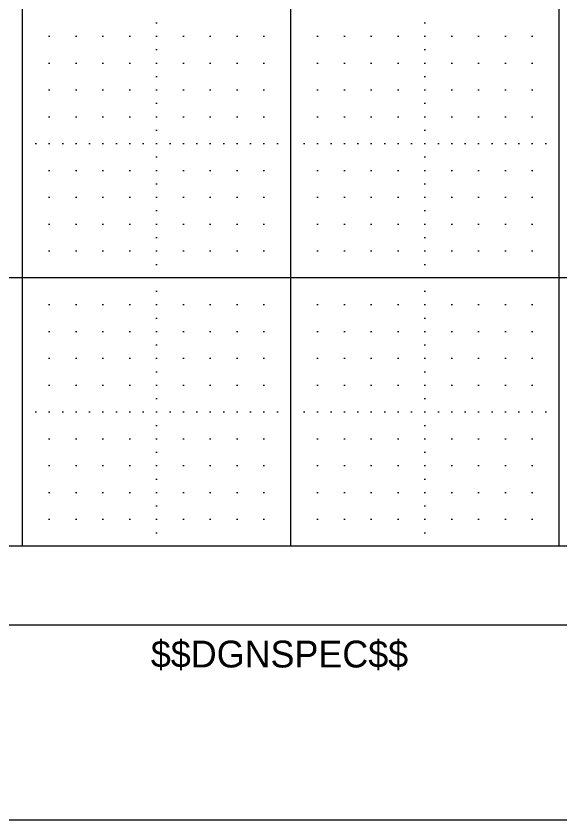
# Model space of a CAD drawing. Extents: x -1.6 to 32.7, y -1.7 to 21.9.
# Drawn here: x 21.721 to 23.748, y -0.727 to 2.268 of the extents above; entities that cross this region are included whole.
import ezdxf

# ---------------------------------------------------------------- set-up
doc = ezdxf.new("R2010")
doc.units = 0
for name, color, linetype in [('Level 1', 7, 'Continuous'), ('Level 4', 7, 'Continuous'), ('Level 48', 7, 'Continuous'), ('Level 5', 7, 'Continuous'), ('Level 63', 7, 'Continuous'), ('R_Border_Dark', 7, 'Continuous')]:
    doc.layers.add(name, color=color, linetype=linetype)

msp = doc.modelspace()

# ---------------------------------------------------------------- linework, layer by layer
at = {"layer": 'Level 1'}
msp.add_line((31.617, -0.001), (-0.001, -0.001), dxfattribs=at)
msp.add_lwpolyline([(0.745, 11.3072), (30.745, 11.3072), (30.745, 0.293), (0.745, 0.293)], close=True, dxfattribs=at)
at = {"layer": 'Level 4'}
msp.add_line((31.617, 0.293), (-0.001, 0.293), dxfattribs=at)
at = {"layer": 'Level 5'}
for p, q in [((22.2425, 2.243), (22.2475, 2.243)), ((23.2425, 2.243), (23.2475, 2.243)), ((21.8425, 2.193), (21.8475, 2.193)), ((21.9425, 2.193), (21.9475, 2.193)), ((22.0425, 2.193), (22.0475, 2.193)), ((22.1425, 2.193), (22.1475, 2.193)), ((22.2425, 2.193), (22.2475, 2.193)), ((22.3425, 2.193), (22.3475, 2.193)), ((22.4425, 2.193), (22.4475, 2.193)), ((22.5425, 2.193), (22.5475, 2.193)), ((22.6425, 2.193), (22.6475, 2.193)), ((22.8425, 2.193), (22.8475, 2.193)), ((22.9425, 2.193), (22.9475, 2.193)), ((23.0425, 2.193), (23.0475, 2.193)), ((23.1425, 2.193), (23.1475, 2.193)), ((23.2425, 2.193), (23.2475, 2.193)), ((23.3425, 2.193), (23.3475, 2.193)), ((23.4425, 2.193), (23.4475, 2.193)), ((23.5425, 2.193), (23.5475, 2.193)), ((23.6425, 2.193), (23.6475, 2.193)), ((22.2425, 2.143), (22.2475, 2.143)), ((23.2425, 2.143), (23.2475, 2.143)), ((21.8425, 2.093), (21.8475, 2.093)), ((21.9425, 2.093), (21.9475, 2.093)), ((22.0425, 2.093), (22.0475, 2.093)), ((22.1425, 2.093), (22.1475, 2.093)), ((22.2425, 2.093), (22.2475, 2.093)), ((22.3425, 2.093), (22.3475, 2.093)), ((22.4425, 2.093), (22.4475, 2.093)), ((22.5425, 2.093), (22.5475, 2.093)), ((22.6425, 2.093), (22.6475, 2.093)), ((22.8425, 2.093), (22.8475, 2.093)), ((22.9425, 2.093), (22.9475, 2.093)), ((23.0425, 2.093), (23.0475, 2.093)), ((23.1425, 2.093), (23.1475, 2.093)), ((23.2425, 2.093), (23.2475, 2.093)), ((23.3425, 2.093), (23.3475, 2.093)), ((23.4425, 2.093), (23.4475, 2.093)), ((23.5425, 2.093), (23.5475, 2.093)), ((23.6425, 2.093), (23.6475, 2.093)), ((22.2425, 2.043), (22.2475, 2.043)), ((23.2425, 2.043), (23.2475, 2.043)), ((21.8425, 1.993), (21.8475, 1.993)), ((21.9425, 1.993), (21.9475, 1.993)), ((22.0425, 1.993), (22.0475, 1.993)), ((22.1425, 1.993), (22.1475, 1.993)), ((22.2425, 1.993), (22.2475, 1.993)), ((22.3425, 1.993), (22.3475, 1.993)), ((22.4425, 1.993), (22.4475, 1.993)), ((22.5425, 1.993), (22.5475, 1.993)), ((22.6425, 1.993), (22.6475, 1.993)), ((22.8425, 1.993), (22.8475, 1.993)), ((22.9425, 1.993), (22.9475, 1.993)), ((23.0425, 1.993), (23.0475, 1.993)), ((23.1425, 1.993), (23.1475, 1.993)), ((23.2425, 1.993), (23.2475, 1.993)), ((23.3425, 1.993), (23.3475, 1.993)), ((23.4425, 1.993), (23.4475, 1.993)), ((23.5425, 1.993), (23.5475, 1.993)), ((23.6425, 1.993), (23.6475, 1.993)), ((22.2425, 1.943), (22.2475, 1.943)), ((23.2425, 1.943), (23.2475, 1.943)), ((21.8425, 1.893), (21.8475, 1.893)), ((21.9425, 1.893), (21.9475, 1.893)), ((22.0425, 1.893), (22.0475, 1.893)), ((22.1425, 1.893), (22.1475, 1.893)), ((22.2425, 1.893), (22.2475, 1.893)), ((22.3425, 1.893), (22.3475, 1.893)), ((22.4425, 1.893), (22.4475, 1.893)), ((22.5425, 1.893), (22.5475, 1.893)), ((22.6425, 1.893), (22.6475, 1.893)), ((22.8425, 1.893), (22.8475, 1.893)), ((22.9425, 1.893), (22.9475, 1.893)), ((23.0425, 1.893), (23.0475, 1.893)), ((23.1425, 1.893), (23.1475, 1.893)), ((23.2425, 1.893), (23.2475, 1.893)), ((23.3425, 1.893), (23.3475, 1.893)), ((23.4425, 1.893), (23.4475, 1.893)), ((23.5425, 1.893), (23.5475, 1.893)), ((23.6425, 1.893), (23.6475, 1.893)), ((22.2425, 1.843), (22.2475, 1.843)), ((23.2425, 1.843), (23.2475, 1.843)), ((21.7925, 1.793), (21.7975, 1.793)), ((21.8425, 1.793), (21.8475, 1.793)), ((21.8925, 1.793), (21.8975, 1.793)), ((21.9425, 1.793), (21.9475, 1.793)), ((21.9925, 1.793), (21.9975, 1.793)), ((22.0425, 1.793), (22.0475, 1.793)), ((22.0925, 1.793), (22.0975, 1.793)), ((22.1425, 1.793), (22.1475, 1.793)), ((22.1925, 1.793), (22.1975, 1.793)), ((22.2425, 1.793), (22.2475, 1.793)), ((22.2925, 1.793), (22.2975, 1.793)), ((22.3425, 1.793), (22.3475, 1.793)), ((22.3925, 1.793), (22.3975, 1.793)), ((22.4425, 1.793), (22.4475, 1.793)), ((22.4925, 1.793), (22.4975, 1.793)), ((22.5425, 1.793), (22.5475, 1.793)), ((22.5925, 1.793), (22.5975, 1.793)), ((22.6425, 1.793), (22.6475, 1.793)), ((22.6925, 1.793), (22.6975, 1.793)), ((22.7925, 1.793), (22.7975, 1.793)), ((22.8425, 1.793), (22.8475, 1.793)), ((22.8925, 1.793), (22.8975, 1.793)), ((22.9425, 1.793), (22.9475, 1.793)), ((22.9925, 1.793), (22.9975, 1.793)), ((23.0425, 1.793), (23.0475, 1.793)), ((23.0925, 1.793), (23.0975, 1.793)), ((23.1425, 1.793), (23.1475, 1.793)), ((23.1925, 1.793), (23.1975, 1.793)), ((23.2425, 1.793), (23.2475, 1.793)), ((23.2925, 1.793), (23.2975, 1.793)), ((23.3425, 1.793), (23.3475, 1.793)), ((23.3925, 1.793), (23.3975, 1.793)), ((23.4425, 1.793), (23.4475, 1.793)), ((23.4925, 1.793), (23.4975, 1.793)), ((23.5425, 1.793), (23.5475, 1.793)), ((23.5925, 1.793), (23.5975, 1.793)), ((23.6425, 1.793), (23.6475, 1.793)), ((23.6925, 1.793), (23.6975, 1.793)), ((22.2425, 1.743), (22.2475, 1.743)), ((23.2425, 1.743), (23.2475, 1.743)), ((21.8425, 1.693), (21.8475, 1.693)), ((21.9425, 1.693), (21.9475, 1.693)), ((22.0425, 1.693), (22.0475, 1.693)), ((22.1425, 1.693), (22.1475, 1.693)), ((22.2425, 1.693), (22.2475, 1.693)), ((22.3425, 1.693), (22.3475, 1.693)), ((22.4425, 1.693), (22.4475, 1.693)), ((22.5425, 1.693), (22.5475, 1.693)), ((22.6425, 1.693), (22.6475, 1.693)), ((22.8425, 1.693), (22.8475, 1.693)), ((22.9425, 1.693), (22.9475, 1.693)), ((23.0425, 1.693), (23.0475, 1.693)), ((23.1425, 1.693), (23.1475, 1.693)), ((23.2425, 1.693), (23.2475, 1.693)), ((23.3425, 1.693), (23.3475, 1.693)), ((23.4425, 1.693), (23.4475, 1.693)), ((23.5425, 1.693), (23.5475, 1.693)), ((23.6425, 1.693), (23.6475, 1.693)), ((22.2425, 1.643), (22.2475, 1.643)), ((23.2425, 1.643), (23.2475, 1.643)), ((21.8425, 1.593), (21.8475, 1.593)), ((21.9425, 1.593), (21.9475, 1.593)), ((22.0425, 1.593), (22.0475, 1.593)), ((22.1425, 1.593), (22.1475, 1.593)), ((22.2425, 1.593), (22.2475, 1.593)), ((22.3425, 1.593), (22.3475, 1.593)), ((22.4425, 1.593), (22.4475, 1.593)), ((22.5425, 1.593), (22.5475, 1.593)), ((22.6425, 1.593), (22.6475, 1.593)), ((22.8425, 1.593), (22.8475, 1.593)), ((22.9425, 1.593), (22.9475, 1.593)), ((23.0425, 1.593), (23.0475, 1.593)), ((23.1425, 1.593), (23.1475, 1.593)), ((23.2425, 1.593), (23.2475, 1.593)), ((23.3425, 1.593), (23.3475, 1.593)), ((23.4425, 1.593), (23.4475, 1.593)), ((23.5425, 1.593), (23.5475, 1.593)), ((23.6425, 1.593), (23.6475, 1.593)), ((22.2425, 1.543), (22.2475, 1.543)), ((23.2425, 1.543), (23.2475, 1.543)), ((21.8425, 1.493), (21.8475, 1.493)), ((21.9425, 1.493), (21.9475, 1.493)), ((22.0425, 1.493), (22.0475, 1.493)), ((22.1425, 1.493), (22.1475, 1.493)), ((22.2425, 1.493), (22.2475, 1.493)), ((22.3425, 1.493), (22.3475, 1.493)), ((22.4425, 1.493), (22.4475, 1.493)), ((22.5425, 1.493), (22.5475, 1.493)), ((22.6425, 1.493), (22.6475, 1.493)), ((22.8425, 1.493), (22.8475, 1.493)), ((22.9425, 1.493), (22.9475, 1.493)), ((23.0425, 1.493), (23.0475, 1.493)), ((23.1425, 1.493), (23.1475, 1.493)), ((23.2425, 1.493), (23.2475, 1.493)), ((23.3425, 1.493), (23.3475, 1.493)), ((23.4425, 1.493), (23.4475, 1.493)), ((23.5425, 1.493), (23.5475, 1.493)), ((23.6425, 1.493), (23.6475, 1.493)), ((22.2425, 1.443), (22.2475, 1.443)), ((23.2425, 1.443), (23.2475, 1.443)), ((21.8425, 1.393), (21.8475, 1.393)), ((21.9425, 1.393), (21.9475, 1.393)), ((22.0425, 1.393), (22.0475, 1.393)), ((22.1425, 1.393), (22.1475, 1.393)), ((22.2425, 1.393), (22.2475, 1.393)), ((22.3425, 1.393), (22.3475, 1.393)), ((22.4425, 1.393), (22.4475, 1.393)), ((22.5425, 1.393), (22.5475, 1.393)), ((22.6425, 1.393), (22.6475, 1.393)), ((22.8425, 1.393), (22.8475, 1.393)), ((22.9425, 1.393), (22.9475, 1.393)), ((23.0425, 1.393), (23.0475, 1.393)), ((23.1425, 1.393), (23.1475, 1.393)), ((23.2425, 1.393), (23.2475, 1.393)), ((23.3425, 1.393), (23.3475, 1.393)), ((23.4425, 1.393), (23.4475, 1.393)), ((23.5425, 1.393), (23.5475, 1.393)), ((23.6425, 1.393), (23.6475, 1.393)), ((22.2425, 1.343), (22.2475, 1.343)), ((23.2425, 1.343), (23.2475, 1.343)), ((22.2425, 1.243), (22.2475, 1.243)), ((23.2425, 1.243), (23.2475, 1.243)), ((21.8425, 1.193), (21.8475, 1.193)), ((21.9425, 1.193), (21.9475, 1.193)), ((22.0425, 1.193), (22.0475, 1.193)), ((22.1425, 1.193), (22.1475, 1.193)), ((22.2425, 1.193), (22.2475, 1.193)), ((22.3425, 1.193), (22.3475, 1.193)), ((22.4425, 1.193), (22.4475, 1.193)), ((22.5425, 1.193), (22.5475, 1.193)), ((22.6425, 1.193), (22.6475, 1.193)), ((22.8425, 1.193), (22.8475, 1.193)), ((22.9425, 1.193), (22.9475, 1.193)), ((23.0425, 1.193), (23.0475, 1.193)), ((23.1425, 1.193), (23.1475, 1.193)), ((23.2425, 1.193), (23.2475, 1.193)), ((23.3425, 1.193), (23.3475, 1.193)), ((23.4425, 1.193), (23.4475, 1.193)), ((23.5425, 1.193), (23.5475, 1.193)), ((23.6425, 1.193), (23.6475, 1.193)), ((22.2425, 1.143), (22.2475, 1.143)), ((23.2425, 1.143), (23.2475, 1.143)), ((21.8425, 1.093), (21.8475, 1.093)), ((21.9425, 1.093), (21.9475, 1.093)), ((22.0425, 1.093), (22.0475, 1.093)), ((22.1425, 1.093), (22.1475, 1.093)), ((22.2425, 1.093), (22.2475, 1.093)), ((22.3425, 1.093), (22.3475, 1.093)), ((22.4425, 1.093), (22.4475, 1.093)), ((22.5425, 1.093), (22.5475, 1.093)), ((22.6425, 1.093), (22.6475, 1.093)), ((22.8425, 1.093), (22.8475, 1.093)), ((22.9425, 1.093), (22.9475, 1.093)), ((23.0425, 1.093), (23.0475, 1.093)), ((23.1425, 1.093), (23.1475, 1.093)), ((23.2425, 1.093), (23.2475, 1.093)), ((23.3425, 1.093), (23.3475, 1.093)), ((23.4425, 1.093), (23.4475, 1.093)), ((23.5425, 1.093), (23.5475, 1.093)), ((23.6425, 1.093), (23.6475, 1.093)), ((22.2425, 1.043), (22.2475, 1.043)), ((23.2425, 1.043), (23.2475, 1.043)), ((21.8425, 0.993), (21.8475, 0.993)), ((21.9425, 0.993), (21.9475, 0.993)), ((22.0425, 0.993), (22.0475, 0.993)), ((22.1425, 0.993), (22.1475, 0.993)), ((22.2425, 0.993), (22.2475, 0.993)), ((22.3425, 0.993), (22.3475, 0.993)), ((22.4425, 0.993), (22.4475, 0.993)), ((22.5425, 0.993), (22.5475, 0.993)), ((22.6425, 0.993), (22.6475, 0.993)), ((22.8425, 0.993), (22.8475, 0.993)), ((22.9425, 0.993), (22.9475, 0.993)), ((23.0425, 0.993), (23.0475, 0.993)), ((23.1425, 0.993), (23.1475, 0.993)), ((23.2425, 0.993), (23.2475, 0.993)), ((23.3425, 0.993), (23.3475, 0.993)), ((23.4425, 0.993), (23.4475, 0.993)), ((23.5425, 0.993), (23.5475, 0.993)), ((23.6425, 0.993), (23.6475, 0.993)), ((22.2425, 0.943), (22.2475, 0.943)), ((23.2425, 0.943), (23.2475, 0.943)), ((21.8425, 0.893), (21.8475, 0.893)), ((21.9425, 0.893), (21.9475, 0.893)), ((22.0425, 0.893), (22.0475, 0.893)), ((22.1425, 0.893), (22.1475, 0.893)), ((22.2425, 0.893), (22.2475, 0.893)), ((22.3425, 0.893), (22.3475, 0.893)), ((22.4425, 0.893), (22.4475, 0.893)), ((22.5425, 0.893), (22.5475, 0.893)), ((22.6425, 0.893), (22.6475, 0.893)), ((22.8425, 0.893), (22.8475, 0.893)), ((22.9425, 0.893), (22.9475, 0.893)), ((23.0425, 0.893), (23.0475, 0.893)), ((23.1425, 0.893), (23.1475, 0.893)), ((23.2425, 0.893), (23.2475, 0.893)), ((23.3425, 0.893), (23.3475, 0.893)), ((23.4425, 0.893), (23.4475, 0.893)), ((23.5425, 0.893), (23.5475, 0.893)), ((23.6425, 0.893), (23.6475, 0.893)), ((22.2425, 0.843), (22.2475, 0.843)), ((23.2425, 0.843), (23.2475, 0.843)), ((21.7925, 0.793), (21.7975, 0.793)), ((21.8425, 0.793), (21.8475, 0.793)), ((21.8925, 0.793), (21.8975, 0.793)), ((21.9425, 0.793), (21.9475, 0.793)), ((21.9925, 0.793), (21.9975, 0.793)), ((22.0425, 0.793), (22.0475, 0.793)), ((22.0925, 0.793), (22.0975, 0.793)), ((22.1425, 0.793), (22.1475, 0.793)), ((22.1925, 0.793), (22.1975, 0.793)), ((22.2425, 0.793), (22.2475, 0.793)), ((22.2925, 0.793), (22.2975, 0.793)), ((22.3425, 0.793), (22.3475, 0.793)), ((22.3925, 0.793), (22.3975, 0.793)), ((22.4425, 0.793), (22.4475, 0.793)), ((22.4925, 0.793), (22.4975, 0.793)), ((22.5425, 0.793), (22.5475, 0.793)), ((22.5925, 0.793), (22.5975, 0.793)), ((22.6425, 0.793), (22.6475, 0.793)), ((22.6925, 0.793), (22.6975, 0.793)), ((22.7925, 0.793), (22.7975, 0.793)), ((22.8425, 0.793), (22.8475, 0.793)), ((22.8925, 0.793), (22.8975, 0.793)), ((22.9425, 0.793), (22.9475, 0.793)), ((22.9925, 0.793), (22.9975, 0.793)), ((23.0425, 0.793), (23.0475, 0.793)), ((23.0925, 0.793), (23.0975, 0.793)), ((23.1425, 0.793), (23.1475, 0.793)), ((23.1925, 0.793), (23.1975, 0.793)), ((23.2425, 0.793), (23.2475, 0.793)), ((23.2925, 0.793), (23.2975, 0.793)), ((23.3425, 0.793), (23.3475, 0.793)), ((23.3925, 0.793), (23.3975, 0.793)), ((23.4425, 0.793), (23.4475, 0.793)), ((23.4925, 0.793), (23.4975, 0.793)), ((23.5425, 0.793), (23.5475, 0.793)), ((23.5925, 0.793), (23.5975, 0.793)), ((23.6425, 0.793), (23.6475, 0.793)), ((23.6925, 0.793), (23.6975, 0.793)), ((22.2425, 0.743), (22.2475, 0.743)), ((23.2425, 0.743), (23.2475, 0.743)), ((21.8425, 0.693), (21.8475, 0.693)), ((21.9425, 0.693), (21.9475, 0.693)), ((22.0425, 0.693), (22.0475, 0.693)), ((22.1425, 0.693), (22.1475, 0.693)), ((22.2425, 0.693), (22.2475, 0.693)), ((22.3425, 0.693), (22.3475, 0.693)), ((22.4425, 0.693), (22.4475, 0.693)), ((22.5425, 0.693), (22.5475, 0.693)), ((22.6425, 0.693), (22.6475, 0.693)), ((22.8425, 0.693), (22.8475, 0.693)), ((22.9425, 0.693), (22.9475, 0.693)), ((23.0425, 0.693), (23.0475, 0.693)), ((23.1425, 0.693), (23.1475, 0.693)), ((23.2425, 0.693), (23.2475, 0.693)), ((23.3425, 0.693), (23.3475, 0.693)), ((23.4425, 0.693), (23.4475, 0.693)), ((23.5425, 0.693), (23.5475, 0.693)), ((23.6425, 0.693), (23.6475, 0.693)), ((22.2425, 0.643), (22.2475, 0.643)), ((23.2425, 0.643), (23.2475, 0.643)), ((21.8425, 0.593), (21.8475, 0.593)), ((21.9425, 0.593), (21.9475, 0.593)), ((22.0425, 0.593), (22.0475, 0.593)), ((22.1425, 0.593), (22.1475, 0.593)), ((22.2425, 0.593), (22.2475, 0.593)), ((22.3425, 0.593), (22.3475, 0.593)), ((22.4425, 0.593), (22.4475, 0.593)), ((22.5425, 0.593), (22.5475, 0.593)), ((22.6425, 0.593), (22.6475, 0.593)), ((22.8425, 0.593), (22.8475, 0.593)), ((22.9425, 0.593), (22.9475, 0.593)), ((23.0425, 0.593), (23.0475, 0.593)), ((23.1425, 0.593), (23.1475, 0.593)), ((23.2425, 0.593), (23.2475, 0.593)), ((23.3425, 0.593), (23.3475, 0.593)), ((23.4425, 0.593), (23.4475, 0.593)), ((23.5425, 0.593), (23.5475, 0.593)), ((23.6425, 0.593), (23.6475, 0.593)), ((22.2425, 0.543), (22.2475, 0.543)), ((23.2425, 0.543), (23.2475, 0.543)), ((21.8425, 0.493), (21.8475, 0.493)), ((21.9425, 0.493), (21.9475, 0.493)), ((22.0425, 0.493), (22.0475, 0.493)), ((22.1425, 0.493), (22.1475, 0.493)), ((22.2425, 0.493), (22.2475, 0.493)), ((22.3425, 0.493), (22.3475, 0.493)), ((22.4425, 0.493), (22.4475, 0.493)), ((22.5425, 0.493), (22.5475, 0.493)), ((22.6425, 0.493), (22.6475, 0.493)), ((22.8425, 0.493), (22.8475, 0.493)), ((22.9425, 0.493), (22.9475, 0.493)), ((23.0425, 0.493), (23.0475, 0.493)), ((23.1425, 0.493), (23.1475, 0.493)), ((23.2425, 0.493), (23.2475, 0.493)), ((23.3425, 0.493), (23.3475, 0.493)), ((23.4425, 0.493), (23.4475, 0.493)), ((23.5425, 0.493), (23.5475, 0.493)), ((23.6425, 0.493), (23.6475, 0.493)), ((22.2425, 0.443), (22.2475, 0.443)), ((23.2425, 0.443), (23.2475, 0.443)), ((21.8425, 0.393), (21.8475, 0.393)), ((21.9425, 0.393), (21.9475, 0.393)), ((22.0425, 0.393), (22.0475, 0.393)), ((22.1425, 0.393), (22.1475, 0.393)), ((22.2425, 0.393), (22.2475, 0.393)), ((22.3425, 0.393), (22.3475, 0.393)), ((22.4425, 0.393), (22.4475, 0.393)), ((22.5425, 0.393), (22.5475, 0.393)), ((22.6425, 0.393), (22.6475, 0.393)), ((22.8425, 0.393), (22.8475, 0.393)), ((22.9425, 0.393), (22.9475, 0.393)), ((23.0425, 0.393), (23.0475, 0.393)), ((23.1425, 0.393), (23.1475, 0.393)), ((23.2425, 0.393), (23.2475, 0.393)), ((23.3425, 0.393), (23.3475, 0.393)), ((23.4425, 0.393), (23.4475, 0.393)), ((23.5425, 0.393), (23.5475, 0.393)), ((23.6425, 0.393), (23.6475, 0.393)), ((22.2425, 0.343), (22.2475, 0.343)), ((23.2425, 0.343), (23.2475, 0.343))]:
    msp.add_line(p, q, dxfattribs=at)
at = {"layer": 'Level 63'}
msp.add_lwpolyline([(-1.598, -0.727), (32.402, -0.727), (32.402, 21.273), (-1.598, 21.273)], close=True, dxfattribs=at)
msp.add_lwpolyline([(30.745, 8.293), (30.745, 0.293), (0.745, 0.293), (0.745, 8.293)], dxfattribs=at)
at = {"layer": 'R_Border_Dark'}
for p, q in [((21.745, 0.293), (21.745, 11.3072)), ((22.745, 0.293), (22.745, 11.3072)), ((23.745, 0.293), (23.745, 11.3072)), ((31.617, 1.293), (-0.001, 1.293))]:
    msp.add_line(p, q, dxfattribs=at)
msp.add_lwpolyline([(30.745, 8.293), (30.745, 0.293), (0.745, 0.293), (0.745, 8.293)], dxfattribs=at)

# ---------------------------------------------------------------- texts
at = {"layer": 'Level 48'}
msp.add_text('$$DGNSPEC$$', height=0.100002, dxfattribs=at).set_placement((22.2236, -0.159))

doc.saveas('drawing.dxf')
